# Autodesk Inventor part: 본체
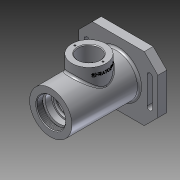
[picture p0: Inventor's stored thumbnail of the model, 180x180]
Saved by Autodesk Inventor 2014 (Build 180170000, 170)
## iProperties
Created: 2017-10
Part Number: 본체
Material: 알루미늄 6061
Document SubType Name: Modeling
Designer: net
Density: 2.71 g/cm^3
Appearance: 알루미늄 - 평지
Mass: 789.296 g
Surface Area: 668.608 cm^2
Volume: 291.253 cm^3
Author: net
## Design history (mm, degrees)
sketch "스케치1"
  geometry: L1 (-58, 47)-(58, 47); L2 (58, 47)-(58, -47); L3 (58, -47)-(-58, -47); L4 (-58, -47)-(-58, 47); L5 (-46, 20)-(-46, -20); L6 (-50, 20)-(-50, -20); L7 (-42, -20)-(-42, 20); L8 (46, 20)-(46, -20); L9 (42, 20)-(42, -20); L10 (50, -20)-(50, 20); A1 r 4 centre (-46, 20) between (-42, 20) and (-50, 20); A2 r 4 centre (-46, -20) between (-50, -20) and (-42, -20); A3 r 4 centre (46, 20) between (50, 20) and (42, 20); A4 r 4 centre (46, -20) between (42, -20) and (50, -20); 5 further points
  constraints: 24 end point, 8 point on circle, 8 tangent, 6 parallel, 4 centre point, 4 midpoint, 3 horizontal alignment, 1 horizontal, 1 perpendicular, 1 vertical alignment
  dimensions: "d0" = 94 distance of L1.end L2.end; "d1" = 116 distance of L1.start L1.end; "d2" = 4 radius of A3; "d3" = 4 radius of A1; "d4" = 40 distance of L8.end L8.start; "d5" = 40 distance of L5.end L5.start; "d6" = 46 distance of point (0, 0) point (-46, 0); "d7" = 92 distance of point (46, 0) point (-46, 0)
extrude "돌출1" new body sketch "스케치1" distance "d8" = 13; taper "d9" = 0 deg
sketch "스케치2"
  geometry: C1 r 31 at (0, 0); 1 further point
  constraints: 1 centre point, 1 coincident
  dimensions: "d10" = 62 diameter of C1
extrude "돌출2" join sketch "스케치2" distance "d11" = 99; taper "d12" = 0 deg
sketch "스케치3"
  geometry: C1 r 35 at (0, 0); 1 further point
  constraints: 1 centre point, 1 coincident
  dimensions: "d13" = 70 diameter of C1
extrude "돌출3" join sketch "스케치3" distance "d14" = 3; taper "d15" = 0 deg
sketch "스케치4"
  geometry: L1 (-35, -3)-(35, -3) reference; L2 (31, 112)-(-31, 112) reference; L3 (0, 112)-(0, -3); L4 (21, 112)-(21, 103); L5 (21, 103)-(24, 103); L6 (24, 103)-(24, 100); L7 (24, 100)-(20, 100); L8 (20, 100)-(20, 91); L9 (20, 91)-(17.5, 91); L10 (17.5, 91)-(17.5, 87.75); L11 (17.5, 87.75)-(18.5, 87.75); L12 (18.5, 87.75)-(18.5, 86); L13 (18.5, 86)-(17.5, 86); L14 (17.5, 86)-(17.5, 75); L15 (17.5, 75)-(26, 75); L16 (26, 75)-(26, 37); L17 (26, 37)-(17.5, 37); L18 (17.5, 37)-(17.5, 26); L19 (17.5, 26)-(16.5, 26); L20 (16.5, 26)-(16.5, 21); L21 (16.5, 21)-(10, 21); L22 (10, 21)-(10, 18.3); L23 (10, 18.3)-(12.5, 18.3); L24 (12.5, 18.3)-(12.5, 11); L25 (12.5, 11)-(16, 11); L26 (16, 11)-(22, -3); 1 further point
  constraints: 48 end point, 17 parallel, 4 perpendicular, 2 collinear, 2 midpoint, 2 point on line, 1 horizontal
  dimensions: "d69" = 42 diameter of L4 L3; "d70" = 48 diameter of L6 L3; "d71" = 40 diameter of L8 L3; "d72" = 35 diameter of L10 L3; "d73" = 37 diameter of L12 L3; "d74" = 52 diameter of L16 L3; "d75" = 33 diameter of L20 L3; "d76" = 20 diameter of L22 L3; "d77" = 25 diameter of L24 L3; "d78" = 32 diameter of L25.end L3; "d79" = 44 diameter of L26.end L3; "d80" = 12 distance between parallel lines of L7 L2; "d81" = 3 distance of L5.end L6.end; "d82" = 21 distance between parallel lines of L2 L9; "d83" = 26 distance from line of L2 L13.end; "d84" = 1.75 distance of L11.end L12.end; "d85" = 11 distance from line of L15 L12.end; "d86" = 38 distance between parallel lines of L17 L15; "d87" = 11 distance from line of L19.end L17; "d88" = 14 distance between parallel lines of L1 L25; "d100" = 5 distance from line of L21 L18.end; "d102" = 2.7 distance from line of L22.end L21
node "작업 평면1"
sketch "스케치5"
  geometry: L1 (31, 112)-(-31, 112) reference; L2 (58, 0)-(-58, 0) reference; C1 r 25 at (0, 56); 2 further points
  constraints: 1 centre point, 1 midpoint, 1 vertical alignment
  dimensions: "d39" = 50 diameter of C1; "d40" = 56 distance from line of C1.centre L1
extrude "돌출4" join sketch "스케치5" distance "d41" = 50 (= d39); taper "d42" = 0 deg
sketch "스케치6"
  geometry: C1 r 25 at (0, 0) reference; C2 r 16 at (0, 0); 1 further point
  constraints: 1 centre point, 1 coincident
  dimensions: "d43" = 32 diameter of C2
extrude "돌출5" cut sketch "스케치6" distance "d44" = 50 (= d39); taper "d45" = 0 deg
sketch "스케치7"
  geometry: C1 r 16 at (0, 0) reference; C2 r 25 at (0, 0) reference; 1 further point
sketch "스케치8"
  geometry: L1 (0, 94)-(0, 0) reference; L2 (0, 94)-(-13, 94) reference; L3 (-13, 0)-(-13, 94) reference; L4 (0, 0)-(-13, 0) reference; 1 further point
sketch "스케치9"
  geometry: C1 r 16 at (0, 0) reference; 2 further points
  constraints: 1 horizontal alignment
  dimensions: "d46" = 20.5 distance of point (20.5, 0) C1.centre
hole "구멍1" sketch "스케치9" at (20.5, 0) diameter "d47" = 2.459; stored, may be unused: countersink angle "d51" = 90 deg, drill point angle "d53" = 118 deg; dims "d48" = 6, "d49" = 4, "d50" = 2, "d52" = 8
chamfer "모따기1" distance "d57" = 20; stored, may be unused: second distance "d58" = 2, angle "d59" = 45 deg
node "작업 평면2"
sketch "스케치10"
  geometry: L1 (0, 25)-(0, -25) reference; L2 (-16, 56)-(-78, 56) reference; 2 further points
  constraints: 1 other
  dimensions: "d60" = 10 distance from line of point (-10, 0) L1; "d61" = 56 distance from line of point (-10, 0) L2
feature "엠보싱1" sketch "스케치10" dims "d0" = 94, "d1" = 116, "d2" = 4, "d3" = 4, "d4" = 40, "d5" = 40, "d6" = 46, "d7" = 92, "d10" = 62, "d62" = 0.5, "d63" = 0
revolve "회전1" stored, may be unused: angle "d91" = 90 deg
feature "스레드1" dims "d92" = 10, "d93" = 0
chamfer "모따기2" distance "d94" = 1; stored, may be unused: second distance "d95" = 2, angle "d96" = 45 deg
fillet "모깎기1" dims "d97" = 3
fillet "모깎기2" dims "d98" = 3
fillet "모깎기3" dims "d99" = 0.3
chamfer "모따기3" distance "d103" = 0.7; stored, may be unused: second distance "d104" = 2, angle "d105" = 30 deg
node "솔리드1"
pattern_circular "원형 패턴1" dims angle "d55" = 360 deg
other parameters: "d38" = 47
